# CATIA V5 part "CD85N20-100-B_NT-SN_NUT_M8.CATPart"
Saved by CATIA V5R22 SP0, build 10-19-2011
Part number: CD85N20-100-B_NT-SN_NUT_M8
Revision: ANY
Definition: UNKNOWN
Nomenclature: CD85N20-100-B_NT-SN_NUT_M8
Source: Unknown
Bounding box of the stored display mesh (mm): x -6.5 to 6.5, y -7.506 to 7.506, z -2.5 to 2.5
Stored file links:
  D:\PER\CAO_PER_MODIF_2025\CAO_PER_pick&place_2024P\Sous_Ensemble_Flacon\CD85N20-100-B_NT-SN_NUT_M8.CATPart
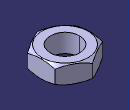
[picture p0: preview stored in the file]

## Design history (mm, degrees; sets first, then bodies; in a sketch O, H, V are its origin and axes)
Body1 "REVOLVE" (main body)
  Solid1: solid without history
